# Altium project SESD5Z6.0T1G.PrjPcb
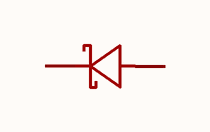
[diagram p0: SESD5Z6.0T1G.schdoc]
1 sheet, 1 parts. Net scope: global (net labels, ports and power ports of the same name join across sheets).

## Sheet SESD5Z6.0T1G.schdoc
size 127 x 101 mm

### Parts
D?  sesd5z6.0t1g  [SOD-523_L1.2-W0.8-LS1.6-RD]  (value not drawn)

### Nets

Not connected (* = marked no-connect by the designer): D? 1(K) 2(A)

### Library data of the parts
D? = sesd5z6.0t1g: 反向截止电压(Vrwm):6V;钳位电压:20.5V;峰值脉冲电流(Ipp):8.8A@8/20us;峰值脉冲功率(Ppp):181W@8/20us;击穿电压(VBR):6.8V;; Manufacturer: JSMSEMI(杰盛微); AddInBom: yes; ModelId: 8f56a03db567494d8f4c9d12aa52a741; ModelName: SOD-523_L1.2-W0.8-H0.7-LS1.6; ModelTransform: 62.992,31.496,0,180,0,0,0,0,0; Reverse Stand-Off Voltage (Vrwm): 6V; Clamping Voltage: 20.5V; Voltage - Breakdown: 6.8V; Reverse Leakage Current (Ir): 10nA; level of protection: IEC 61000-4-4；IEC 61000-4-2; Type: ESD; Junction Capacitance: 70pF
